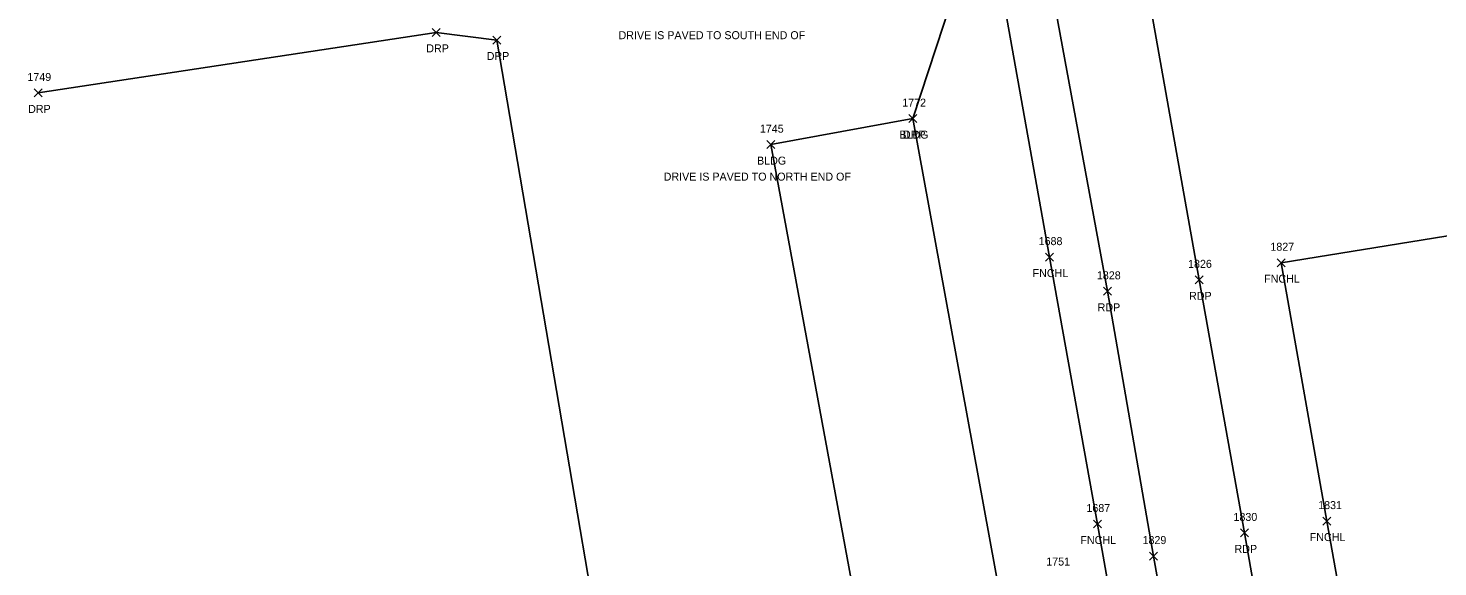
# Model space of a CAD drawing. Extents: x 1481523 to 1489083, y 884156 to 893756.
# Drawn here: x 1486298.7 to 1486651.1, y 888538.8 to 888673.5 of the extents above; entities that cross this region are included whole.
import ezdxf

# ---------------------------------------------------------------- set-up
doc = ezdxf.new("R2010")
doc.units = 0
for name, color, linetype in [('C_I', 7, 'Continuous'), ('L_A', 7, 'Continuous'), ('L_C', 7, 'Continuous'), ('L_I', 7, 'Continuous'), ('L_TIC', 7, 'Continuous'), ('LBC', 7, 'Continuous'), ('LFNC', 7, 'Continuous'), ('P_A', 7, 'Continuous'), ('P_I', 7, 'Continuous'), ('P_TIC', 7, 'Continuous'), ('PET', 7, 'Continuous'), ('R_A', 7, 'Continuous'), ('R_I', 7, 'Continuous'), ('R_TIC', 7, 'Continuous'), ('RDP', 7, 'Continuous')]:
    doc.layers.add(name, color=color, linetype=linetype)

msp = doc.modelspace()

# ---------------------------------------------------------------- linework, layer by layer
at = {"layer": 'L_TIC'}
for points in [[(1486518.89, 888649.91), (1486520.89, 888651.91)], [(1486520.89, 888649.91), (1486518.89, 888651.91)], [(1486518.89, 888649.91), (1486520.89, 888651.91)], [(1486520.89, 888649.91), (1486518.89, 888651.91)], [(1486483.32, 888643.4), (1486485.32, 888645.4)], [(1486485.32, 888643.4), (1486483.32, 888645.4)], [(1486553.04, 888615.26), (1486555.04, 888617.26)], [(1486555.04, 888615.26), (1486553.04, 888617.26)], [(1486610.93, 888613.86), (1486612.93, 888615.86)], [(1486612.93, 888613.86), (1486610.93, 888615.86)], [(1486610.93, 888613.86), (1486612.93, 888615.86)], [(1486612.93, 888613.86), (1486610.93, 888615.86)], [(1486622.3, 888549.21), (1486624.3, 888551.21)], [(1486624.3, 888549.21), (1486622.3, 888551.21)], [(1486564.98, 888548.48), (1486566.98, 888550.48)], [(1486566.98, 888548.48), (1486564.98, 888550.48)]]:
    msp.add_lwpolyline(points, dxfattribs=at)
at = {"layer": 'LBC'}
for points in [[(1486507.89, 888517.06), (1486484.32, 888644.4), (1486519.89, 888650.91)], [(1486507.89, 888517.06), (1486543.14, 888523.63), (1486519.89, 888650.91)]]:
    msp.add_lwpolyline(points, dxfattribs=at)
at = {"layer": 'LFNC'}
for points in [[(1486494.1, 888089.15), (1486542.31, 888096.89), (1486562.09, 888100.11), (1486610.33, 888107.69), (1486643.08, 888113.16), (1486633.4, 888171.45), (1486626.62, 888209.7), (1486614.5, 888277.37), (1486602.35, 888345.54), (1486591.72, 888405.11), (1486588.69, 888421.87), (1486578, 888481.54), (1486565.98, 888549.48), (1486554.04, 888616.26), (1486540.66, 888690.96), (1486537.54, 888707.46), (1486527.52, 888764.64), (1486517.54, 888822.03), (1486505.67, 888889.2), (1486493.41, 888956.36), (1486481.11, 889023.64), (1486470.56, 889080.63), (1486461.7, 889127.71), (1486454.26, 889166.3)], [(1486611.93, 888614.86), (1486729.72, 888633.96), (1486821.77, 888648.41), (1486910.35, 888662.67), (1486965.56, 888671.42), (1487049.78, 888685.11)], [(1486611.93, 888614.86), (1486623.3, 888550.21), (1486633.47, 888493.25), (1486665.01, 888470.64)]]:
    msp.add_lwpolyline(points, dxfattribs=at)
at = {"layer": 'P_TIC'}
for points in [[(1486590.4, 888609.57), (1486592.4, 888611.57)], [(1486592.4, 888609.57), (1486590.4, 888611.57)], [(1486567.55, 888606.7), (1486569.55, 888608.7)], [(1486569.55, 888606.7), (1486567.55, 888608.7)], [(1486601.78, 888546.25), (1486603.78, 888548.25)], [(1486603.78, 888546.25), (1486601.78, 888548.25)], [(1486578.98, 888540.46), (1486580.98, 888542.46)], [(1486580.98, 888540.46), (1486578.98, 888542.46)]]:
    msp.add_lwpolyline(points, dxfattribs=at)
at = {"layer": 'PET'}
for points in [[(1486482.46, 889213.8), (1486493.22, 889156.8), (1486512.17, 889057.76), (1486527.58, 888974.51), (1486542.53, 888889.08), (1486553.79, 888825.37), (1486565.07, 888760.91), (1486577.19, 888690.78), (1486591.4, 888610.57), (1486602.78, 888547.25), (1486614.23, 888481.5), (1486627.06, 888409.28), (1486638.94, 888342.58), (1486654.61, 888252.22), (1486669.1, 888181.27), (1486680.17, 888112.03), (1486680.99, 888105.73)], [(1486459.06, 889211.36), (1486470.75, 889147.47), (1486504.42, 888970.47), (1486519.24, 888886.05), (1486530.77, 888821.38), (1486542.03, 888758.69), (1486549.22, 888711.97), (1486553.24, 888690.65), (1486568.55, 888607.7), (1486579.98, 888541.46), (1486590.64, 888481.54), (1486600.71, 888424.31), (1486604.32, 888404.42), (1486616.77, 888334.61), (1486631.96, 888248.32), (1486646.36, 888167.9), (1486656.21, 888114.83)]]:
    msp.add_lwpolyline(points, dxfattribs=at)
at = {"layer": 'R_TIC'}
for points in [[(1486399.74, 888671.5), (1486401.74, 888673.5)], [(1486401.74, 888671.5), (1486399.74, 888673.5)], [(1486414.84, 888669.58), (1486416.84, 888671.58)], [(1486416.84, 888669.58), (1486414.84, 888671.58)], [(1486300.22, 888656.33), (1486302.22, 888658.33)], [(1486302.22, 888656.33), (1486300.22, 888658.33)], [(1486518.89, 888649.91), (1486520.89, 888651.91)], [(1486520.89, 888649.91), (1486518.89, 888651.91)]]:
    msp.add_lwpolyline(points, dxfattribs=at)
at = {"layer": 'RDP'}
for points in [[(1486519.89, 888650.91), (1486531.41, 888686.34)], [(1486570.58, 888134.65), (1486496.65, 888122.37), (1486474.92, 888261.77), (1486467.85, 888330.77), (1486458.78, 888418.3), (1486415.84, 888670.58), (1486400.74, 888672.5), (1486301.22, 888657.33)]]:
    msp.add_lwpolyline(points, dxfattribs=at)

# ---------------------------------------------------------------- texts
at = {"layer": 'C_I'}
msp.add_text('1751', height=2, dxfattribs=at).set_placement((1486553.2, 888539.09))
at = {"layer": 'L_A'}
for s, p in [('BLDG', (1486516.48, 888645.91)), ('BLDG', (1486516.48, 888645.91)), ('BLDG', (1486480.91, 888639.4)), ('FNCHL', (1486549.79, 888611.26)), ('FNCHL', (1486607.67, 888609.86)), ('FNCHL', (1486607.67, 888609.86)), ('FNCHL', (1486561.73, 888544.48)), ('FNCHL', (1486619.05, 888545.21))]:
    msp.add_text(s, height=2, dxfattribs=at).set_placement(p)
at = {"layer": 'L_C'}
for s, p in [('DRIVE IS PAVED TO SOUTH END OF', (1486446.29, 888670.79)), ('DRIVE IS PAVED TO SOUTH END OF', (1486446.29, 888670.79)), ('DRIVE IS PAVED TO NORTH END OF', (1486457.57, 888635.4))]:
    msp.add_text(s, height=2, dxfattribs=at).set_placement(p)
at = {"layer": 'L_I'}
for s, p in [('1772', (1486517.2, 888653.91)), ('1772', (1486517.2, 888653.91)), ('1745', (1486481.62, 888647.4)), ('1688', (1486551.3, 888619.26)), ('1827', (1486609.23, 888617.86)), ('1827', (1486609.23, 888617.86)), ('1687', (1486563.24, 888552.48)), ('1831', (1486621.17, 888553.21))]:
    msp.add_text(s, height=2, dxfattribs=at).set_placement(p)
at = {"layer": 'P_A'}
for p in [(1486588.89, 888605.57), (1486566.04, 888602.7), (1486600.27, 888542.25)]:
    msp.add_text('RDP', height=2, dxfattribs=at).set_placement(p)
at = {"layer": 'P_I'}
for s, p in [('1826', (1486588.65, 888613.57)), ('1828', (1486565.86, 888610.7)), ('1830', (1486600, 888550.25)), ('1829', (1486577.27, 888544.46))]:
    msp.add_text(s, height=2, dxfattribs=at).set_placement(p)
at = {"layer": 'R_A'}
for p in [(1486398.23, 888667.5), (1486413.33, 888665.58), (1486298.71, 888652.33), (1486517.38, 888645.91)]:
    msp.add_text('DRP', height=2, dxfattribs=at).set_placement(p)
at = {"layer": 'R_I'}
for s, p in [('1749', (1486298.52, 888660.33)), ('1772', (1486517.2, 888653.91))]:
    msp.add_text(s, height=2, dxfattribs=at).set_placement(p)

doc.saveas('drawing.dxf')
